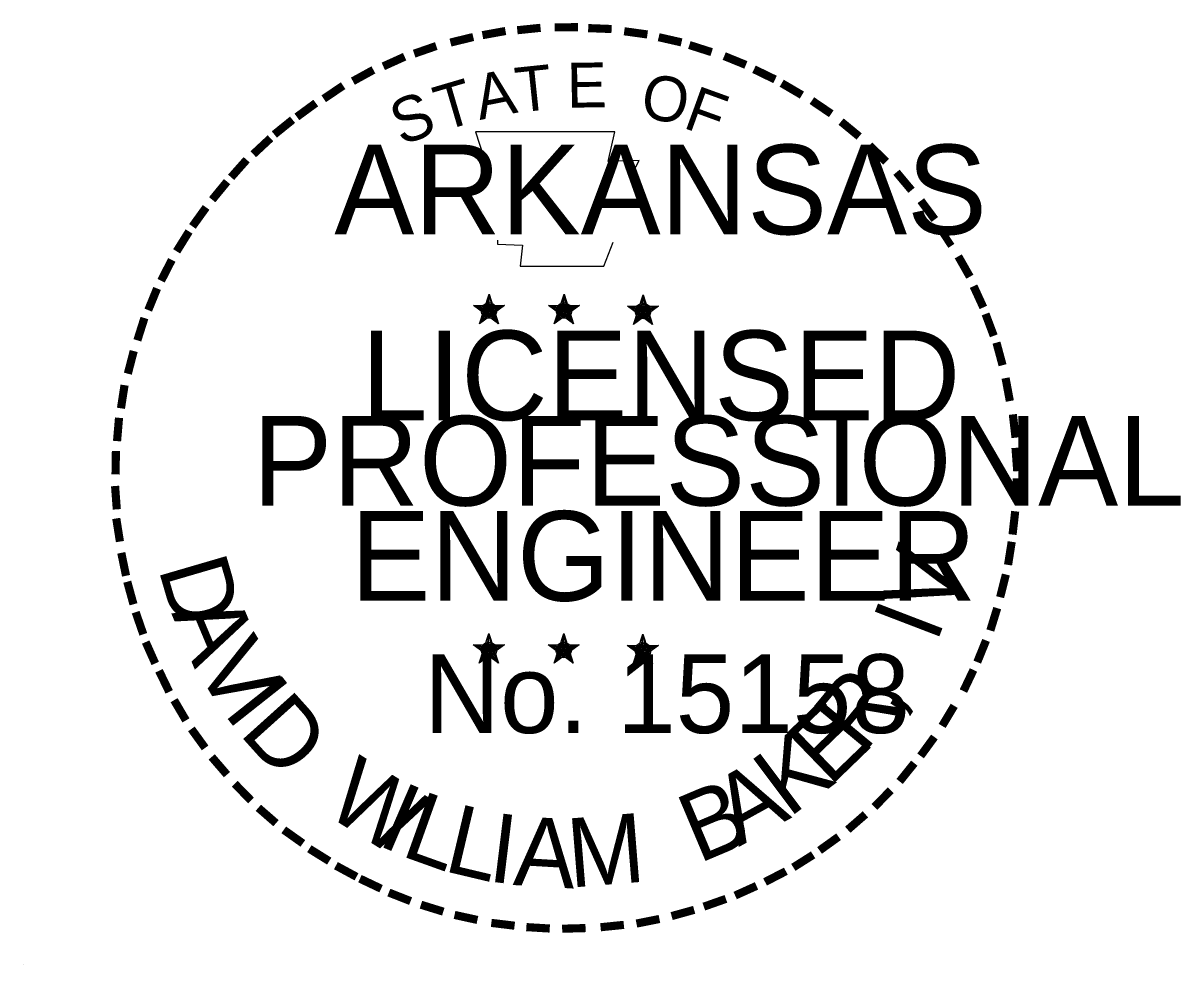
# Model space of a CAD drawing. Extents: x 31847 to 33828, y 52928 to 59118.
# Drawn here: x 33639.1 to 33772.3, y 56397.8 to 56506.1 of the extents above; entities that cross this region are included whole.
import ezdxf

# ---------------------------------------------------------------- set-up
doc = ezdxf.new("R2010")
doc.units = 0
doc.layers.add('R_Border', color=7, linetype='Continuous')
doc.layers.add('R_Border PE', color=7, linetype='Continuous')

msp = doc.modelspace()

# ---------------------------------------------------------------- linework, layer by layer
at = {"layer": 'R_Border'}
msp.add_line((33639.12, 56397.75), (33639.12, 56397.75), dxfattribs=at)
at = {"layer": 'R_Border PE'}
for p, q in [((33692.75, 56474.91), (33692.53, 56473.62)), ((33692.75, 56473.03), (33692.75, 56474.91)), ((33692.75, 56474.91), (33693, 56473.63)), ((33701.36, 56474.91), (33701.14, 56473.62)), ((33701.36, 56473.03), (33701.36, 56474.91)), ((33701.36, 56474.91), (33701.61, 56473.63)), ((33710.45, 56474.85), (33710.24, 56473.55)), ((33710.45, 56472.97), (33710.45, 56474.85)), ((33710.45, 56474.85), (33710.7, 56473.56)), ((33690.95, 56473.6), (33692.75, 56473.03)), ((33690.95, 56473.6), (33692.25, 56473.37)), ((33690.95, 56473.6), (33692.17, 56472.98)), ((33691.63, 56471.5), (33692.75, 56473.03)), ((33691.63, 56471.5), (33692.28, 56472.76)), ((33694.53, 56473.6), (33692.75, 56473.03)), ((33693.84, 56471.5), (33692.75, 56473.03)), ((33694.53, 56473.6), (33693.06, 56473.35)), ((33693.84, 56471.5), (33693.14, 56473)), ((33694.53, 56473.6), (33693.48, 56473.08)), ((33699.56, 56473.6), (33701.36, 56473.03)), ((33699.56, 56473.6), (33700.86, 56473.37)), ((33699.56, 56473.6), (33700.78, 56472.98)), ((33700.24, 56471.5), (33701.36, 56473.03)), ((33700.24, 56471.5), (33700.89, 56472.76)), ((33703.15, 56473.6), (33701.36, 56473.03)), ((33702.45, 56471.5), (33701.36, 56473.03)), ((33703.15, 56473.6), (33701.67, 56473.35)), ((33702.45, 56471.5), (33701.75, 56473)), ((33703.15, 56473.6), (33702.09, 56473.08)), ((33708.65, 56473.54), (33710.45, 56472.97)), ((33708.65, 56473.54), (33709.96, 56473.31)), ((33708.65, 56473.54), (33709.87, 56472.91)), ((33709.34, 56471.44), (33710.45, 56472.97)), ((33709.34, 56471.44), (33709.99, 56472.7)), ((33712.24, 56473.54), (33710.45, 56472.97)), ((33711.55, 56471.44), (33710.45, 56472.97)), ((33712.24, 56473.54), (33710.77, 56473.29)), ((33711.55, 56471.44), (33710.84, 56472.94)), ((33712.24, 56473.54), (33711.19, 56473.02)), ((33691.63, 56471.5), (33692.73, 56472.62)), ((33693.84, 56471.5), (33692.73, 56472.6)), ((33700.24, 56471.5), (33701.35, 56472.62)), ((33702.45, 56471.5), (33701.35, 56472.6)), ((33709.34, 56471.44), (33710.44, 56472.56)), ((33711.55, 56471.44), (33710.44, 56472.54)), ((33692.72, 56435.87), (33692.51, 56434.57)), ((33692.72, 56433.98), (33692.72, 56435.87)), ((33692.72, 56435.87), (33692.98, 56434.58)), ((33701.33, 56435.87), (33701.12, 56434.57)), ((33701.33, 56433.98), (33701.33, 56435.87)), ((33701.33, 56435.87), (33701.58, 56434.58)), ((33710.44, 56435.81), (33710.23, 56434.52)), ((33710.44, 56433.93), (33710.44, 56435.81)), ((33710.44, 56435.81), (33710.69, 56434.53)), ((33690.92, 56434.56), (33692.72, 56433.98)), ((33690.92, 56434.56), (33692.23, 56434.32)), ((33690.92, 56434.56), (33692.15, 56433.93)), ((33694.51, 56434.56), (33692.72, 56433.98)), ((33694.51, 56434.56), (33693.04, 56434.3)), ((33694.51, 56434.56), (33693.46, 56434.03)), ((33699.53, 56434.56), (33701.33, 56433.98)), ((33699.53, 56434.56), (33700.84, 56434.32)), ((33699.53, 56434.56), (33700.75, 56433.93)), ((33703.12, 56434.56), (33701.33, 56433.98)), ((33703.12, 56434.56), (33701.64, 56434.3)), ((33703.12, 56434.56), (33702.07, 56434.03)), ((33708.64, 56434.51), (33710.44, 56433.93)), ((33708.64, 56434.51), (33709.95, 56434.27)), ((33708.64, 56434.51), (33709.86, 56433.88)), ((33712.23, 56434.51), (33710.44, 56433.93)), ((33712.23, 56434.51), (33710.76, 56434.25)), ((33712.23, 56434.51), (33711.18, 56433.98)), ((33691.61, 56432.45), (33692.72, 56433.98)), ((33691.61, 56432.45), (33692.26, 56433.71)), ((33691.61, 56432.45), (33692.71, 56433.57)), ((33693.82, 56432.45), (33692.71, 56433.56)), ((33693.82, 56432.45), (33692.72, 56433.98)), ((33693.82, 56432.45), (33693.12, 56433.95)), ((33700.22, 56432.45), (33701.33, 56433.98)), ((33700.22, 56432.45), (33700.87, 56433.71)), ((33700.22, 56432.45), (33701.32, 56433.57)), ((33702.43, 56432.45), (33701.32, 56433.56)), ((33702.43, 56432.45), (33701.33, 56433.98)), ((33702.43, 56432.45), (33701.72, 56433.95)), ((33709.33, 56432.4), (33710.44, 56433.93)), ((33709.33, 56432.4), (33709.98, 56433.66)), ((33709.33, 56432.4), (33710.43, 56433.52)), ((33711.54, 56432.4), (33710.43, 56433.5)), ((33711.54, 56432.4), (33710.44, 56433.93)), ((33711.54, 56432.4), (33710.83, 56433.9))]:
    msp.add_line(p, q, dxfattribs=at)
for points in [[(33691.16, 56493.6), (33692.54, 56489.34)], [(33709.26, 56488.85), (33709.99, 56490.31), (33706.46, 56490.19), (33707.22, 56493.6), (33691.16, 56493.6)], [(33693.69, 56481.11), (33693.69, 56480.66), (33696.6, 56480.56), (33696.32, 56478.12), (33705.96, 56478.12), (33707, 56480.89)], [(33692.75, 56474.91), (33693.84, 56471.5), (33690.95, 56473.6), (33694.53, 56473.6), (33691.63, 56471.5), (33692.75, 56474.91)], [(33701.36, 56474.91), (33702.45, 56471.5), (33699.56, 56473.6), (33703.15, 56473.6), (33700.24, 56471.5), (33701.36, 56474.91)], [(33710.45, 56474.85), (33711.55, 56471.44), (33708.65, 56473.54), (33712.24, 56473.54), (33709.34, 56471.44), (33710.45, 56474.85)], [(33692.72, 56435.87), (33693.82, 56432.45), (33690.92, 56434.56), (33694.51, 56434.56), (33691.61, 56432.45), (33692.72, 56435.87)], [(33701.33, 56435.87), (33702.43, 56432.45), (33699.53, 56434.56), (33703.12, 56434.56), (33700.22, 56432.45), (33701.33, 56435.87)], [(33710.44, 56435.81), (33711.54, 56432.4), (33708.64, 56434.51), (33712.23, 56434.51), (33709.33, 56432.4), (33710.44, 56435.81)]]:
    msp.add_lwpolyline(points, dxfattribs=at)
for centre, radius in [((33692.74, 56473.03), 0.888), ((33692.74, 56473.03), 0.745), ((33692.74, 56473.03), 0.597), ((33692.74, 56473.03), 0.511), ((33692.74, 56473.03), 0.385), ((33692.74, 56473.03), 0.255), ((33692.74, 56473.03), 0.153), ((33701.35, 56473.03), 0.888), ((33701.35, 56473.03), 0.745), ((33701.35, 56473.03), 0.597), ((33701.35, 56473.03), 0.511), ((33701.35, 56473.03), 0.385), ((33701.35, 56473.03), 0.255), ((33701.35, 56473.03), 0.153), ((33710.45, 56472.97), 0.888), ((33710.45, 56472.97), 0.745), ((33710.45, 56472.97), 0.597), ((33710.45, 56472.97), 0.511), ((33710.45, 56472.97), 0.385), ((33710.45, 56472.97), 0.255), ((33710.45, 56472.97), 0.153), ((33692.72, 56433.98), 0.888), ((33692.72, 56433.98), 0.745), ((33692.72, 56433.98), 0.597), ((33692.72, 56433.98), 0.511), ((33692.72, 56433.98), 0.385), ((33692.72, 56433.98), 0.255), ((33692.72, 56433.98), 0.153), ((33701.32, 56433.98), 0.888), ((33701.32, 56433.98), 0.745), ((33701.32, 56433.98), 0.597), ((33701.32, 56433.98), 0.511), ((33701.32, 56433.98), 0.385), ((33701.32, 56433.98), 0.255), ((33701.32, 56433.98), 0.153), ((33710.44, 56433.93), 0.888), ((33710.44, 56433.93), 0.745), ((33710.44, 56433.93), 0.597), ((33710.44, 56433.93), 0.511), ((33710.44, 56433.93), 0.385), ((33710.44, 56433.93), 0.255), ((33710.44, 56433.93), 0.153)]:
    msp.add_circle(centre, radius, dxfattribs=at)

# ---------------------------------------------------------------- texts
for s, height, rotation, p in [('-', 8.25, 5.8968, (33695.82, 56502.06)), ('-', 8.25, 0.1862, (33699.8, 56502.43)), ('-', 8.25, 357.743, (33703.53, 56502.36)), ('-', 8.25, 13.6302, (33688.57, 56500.65)), ('-', 8.25, 10.2193, (33692.06, 56501.49)), ('-', 8.25, 352.1617, (33707.37, 56502.07)), ('-', 8.25, 347.2049, (33711.07, 56501.48)), ('-', 8.25, 19.1761, (33684.7, 56499.41)), ('-', 8.25, 342.3362, (33714.35, 56500.69)), ('-', 8.25, 24.3072, (33681.43, 56498.02)), ('-', 8.25, 337.8551, (33718.14, 56499.54)), ('-', 8.25, 28.7918, (33678.17, 56496.39)), ('T', 5.16, 6.0228, (33696.02, 56495.8)), ('E', 5.16, 0.8323, (33701.72, 56496.36)), ('-', 8.25, 334.1211, (33721.39, 56498.14)), ('-', 8.25, 34.0636, (33675.09, 56494.48)), ('T', 5.16, 16.4036, (33687.39, 56493.65)), ('A', 5.16, 11.2132, (33691.65, 56494.94)), ('O', 5.16, 350.4515, (33709.99, 56495.28)), ('-', 8.25, 329.6409, (33724.38, 56496.68)), ('S', 5.16, 21.594, (33682.67, 56491.94)), ('F', 5.16, 340.0707, (33714.91, 56494.11)), ('-', 8.25, 36.2317, (33672.11, 56492.45)), ('-', 8.25, 325.8627, (33727.69, 56494.82)), ('-', 8.25, 38.9507, (33669.65, 56490.5)), ('-', 8.25, 320.5297, (33730.84, 56492.62)), ('-', 8.25, 42.9622, (33667.42, 56488.35)), ('-', 8.25, 315.5786, (33733.93, 56490.1)), ('-', 8.25, 48.4231, (33665.11, 56485.88)), ('-', 8.25, 309.8797, (33736.86, 56487.27)), ('-', 8.25, 50.6142, (33663.03, 56483.38)), ('-', 8.25, 54.2325, (33660.9, 56480.45)), ('-', 8.25, 306.6522, (33739.57, 56484.16)), ('-', 8.25, 58.0706, (33659.23, 56477.74)), ('-', 7.22, 303.6753, (33742.07, 56481.24)), ('-', 8.25, 299.6684, (33743.72, 56478.11)), ('-', 8.25, 62.8713, (33657.61, 56474.57)), ('-', 8.25, 67.7743, (33656.28, 56471.42)), ('-', 8.25, 294.6628, (33745.39, 56474.95)), ('-', 8.25, 290.5728, (33746.71, 56471.98)), ('-', 8.25, 72.3945, (33655.15, 56468.17)), ('-', 8.25, 285.1233, (33747.92, 56468.98)), ('-', 8.25, 75.461, (33654.13, 56464.49)), ('-', 8.25, 280.5493, (33748.95, 56465.16)), ('-', 8.25, 81.2013, (33653.45, 56460.81)), ('-', 8.25, 85.1863, (33653.06, 56457.25)), ('-', 8.25, 276.5962, (33749.79, 56461.2)), ('-', 8.25, 89.0622, (33652.93, 56453.63)), ('-', 8.25, 274.3301, (33750.1, 56457.48)), ('-', 8.25, 94.1959, (33653.11, 56449.9)), ('-', 8.25, 269.9407, (33750.27, 56454.22)), ('-', 8.25, 98.9479, (33653.48, 56446.46)), ('-', 8.25, 263.5172, (33750.17, 56450.78)), ('V', 7.94, 72.6573, (33745.35, 56437.41)), ('-', 8.25, 260.9953, (33749.81, 56447.41)), ('-', 8.25, 101.7149, (33654.18, 56442.68)), ('D', 7.94, 286.2848, (33654.64, 56443.39)), ('-', 8.25, 255.7626, (33749.24, 56443.92)), ('-', 8.25, 105.4578, (33655.02, 56439.61)), ('-', 8.25, 109.0874, (33656.12, 56436.36)), ('A', 7.94, 292.7835, (33656.15, 56438.22)), ('I', 7.94, 69.0301, (33744.2, 56434.63)), ('-', 8.25, 252.8681, (33748.31, 56440.2)), ('V', 7.94, 300.7936, (33658.8, 56432.14)), ('-', 8.25, 114.0643, (33657.43, 56433.28)), ('-', 8.25, 247.8887, (33747.16, 56436.73)), ('-', 8.25, 115.7289, (33659.01, 56430.1)), ('R', 7.94, 50.3651, (33735.69, 56421.79)), ('-', 8.25, 244.6197, (33745.81, 56433.49)), ('I', 7.94, 308.3502, (33662.05, 56426.8)), ('D', 7.94, 311.9774, (33663.86, 56424.39)), (',', 7.94, 57.4684, (33739.42, 56426.34)), ('-', 8.25, 120.4471, (33660.85, 56427.07)), ('E', 7.94, 44.0175, (33731.91, 56418.14)), ('-', 8.25, 239.0712, (33743.78, 56429.61)), ('-', 8.25, 125.8934, (33662.93, 56424.18)), ('K', 7.94, 36.9143, (33727.22, 56414.58)), ('-', 8.25, 233.8452, (33741.7, 56426.24)), ('-', 8.25, 130.7181, (33665.31, 56421.34)), ('W', 7.94, 328.0731, (33673.54, 56415.29)), ('-', 8.25, 231.2538, (33739.49, 56423.33)), ('A', 7.94, 28.9042, (33721.46, 56411.3)), ('-', 8.25, 134.2238, (33667.97, 56418.53)), ('I', 7.94, 336.6877, (33679.67, 56411.63)), ('B', 7.94, 22.8589, (33716.84, 56409.37)), ('-', 8.25, 225.7653, (33737.02, 56420.42)), ('L', 7.94, 340.3149, (33682.4, 56410.37)), ('-', 8.25, 138.9338, (33670.68, 56416.13)), ('L', 7.94, 346.6625, (33687.34, 56408.59)), ('-', 8.25, 221.0851, (33734.32, 56417.79)), ('I', 7.94, 353.0101, (33692.46, 56407.38)), ('A', 7.94, 356.6373, (33695.43, 56406.94)), ('M', 7.94, 4.6473, (33702.06, 56406.63)), ('-', 8.25, 144.6463, (33673.55, 56414.04)), ('-', 8.25, 215.7363, (33731.49, 56415.36)), ('-', 8.25, 148.0898, (33676.44, 56412.13)), ('-', 8.25, 212.2491, (33728.74, 56413.36)), ('-', 8.25, 151.5704, (33679.43, 56410.45)), ('-', 8.25, 207.3568, (33725.86, 56411.58)), ('-', 8.25, 154.6002, (33682.12, 56409.18)), ('-', 8.25, 158.5612, (33685.33, 56407.87)), ('-', 8.25, 204.2516, (33722.65, 56409.94)), ('-', 8.25, 162.7983, (33688.88, 56406.77)), ('-', 8.25, 199.4643, (33719.39, 56408.51)), ('-', 8.25, 167.5555, (33692.56, 56405.92)), ('-', 8.25, 191.2858, (33712.2, 56406.25)), ('-', 8.25, 195.4743, (33715.96, 56407.28)), ('-', 8.25, 173.1155, (33696.54, 56405.36)), ('-', 8.25, 176.5183, (33700.4, 56405.08)), ('-', 8.25, 181.5918, (33704.24, 56405.18)), ('-', 8.25, 185.8167, (33708.41, 56405.57))]:
    msp.add_text(s, height=height, rotation=rotation, dxfattribs=at).set_placement(p)
for s, height, p in [('ARKANSAS', 10.312, (33674.93, 56481.8)), ('LICENSED', 10.312, (33678.01, 56460.41)), ('PROFESSIONAL', 10.3125, (33665.51, 56450.59)), ('ENGINEER', 10.312, (33676.79, 56439.64)), ('No. 15158', 9.06, (33685.25, 56424.42)), ('AAMU', 0.000103, (33700.99, 56406.61))]:
    msp.add_text(s, height=height, dxfattribs=at).set_placement(p)

doc.saveas('drawing.dxf')
